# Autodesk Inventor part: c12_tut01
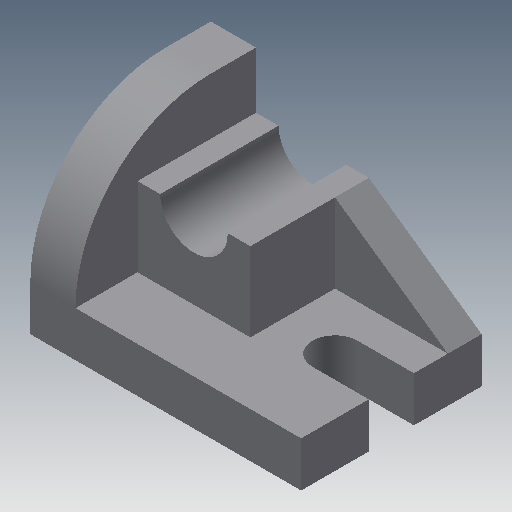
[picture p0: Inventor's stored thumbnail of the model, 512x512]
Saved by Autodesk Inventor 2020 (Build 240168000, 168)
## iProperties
Created: 2001-11
Part Number: c12_tut01
Document SubType Name: Modeling
Designer: Renu Muthoo
Density: 1 g/cm^3
Material: Generic
Appearance: Default
Control State: 0
Master: False
Checked Out: False
Shininess: 77.0
Length Units: 11269
Angle Units: 11279
Time Units: 11290
Mass Units: 11283
Length Display Precision: 3
Angle Display Precision: 2
Density: 0.0
Volumn: 0.0
Area: 0.0
PropertySet Name: Model Information
Author: Renu Muthoo
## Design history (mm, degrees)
sketch "Sketch1"
  geometry: L1 (-48, 36)-(48, 36); L2 (48, -28)-(-48, -28); L3 (-48, -28)-(-48, 36); L4 (48, 12)-(28, 12); L5 (28, -4)-(48, -4); L6 (48, 36)-(48, 12); L7 (48, -4)-(48, -28); A1 r 8 centre (28, 4) between (28, 12) and (28, -4)
  constraints: 14 end point, 4 parallel, 3 perpendicular, 2 point on circle, 2 tangent, 1 centre point, 1 collinear, 1 horizontal
  dimensions: "d0" = 96 distance of L2.start L2.end; "d1" = 64 distance of L2.end L1.start; "d2" = 20 distance of L4.start L4.end; "d3" = 24 distance between parallel lines of L2 L5; "d4" = 16 distance between parallel lines of L4 L5
extrude "Extrusion1" new body sketch "Sketch1" distance "d5" = 16; taper "d6" = 0 deg
sketch "Sketch2"
  geometry: L1 (16, 64)-(64, 64); L2 (64, 64)-(64, 48); L3 (16, 0)-(16, 0); L4 (16, 0)-(16, 64); L5 (0, 64)-(16, 64) reference; L6 (16, 0)-(16, 64) reference; L7 (0, 0)-(16, 0) reference; L8 (0, 0)-(0, 64) reference; A1 r 48 centre (16, 48) between (16, 0) and (64, 48)
  constraints: 8 end point, 3 collinear, 3 perpendicular, 2 point on circle, 2 tangent, 1 centre point, 1 horizontal
  dimensions: "d7" = 64 distance between parallel lines of L2 L8; "d8" = 48 radius of A1
extrude "Extrusion2" join sketch "Sketch2" distance "d9" = 16; taper "d10" = 0 deg
sketch "Sketch3"
  geometry: L1 (16, -44)-(16, -16); L2 (16, -16)-(56, -16); L3 (56, -16)-(56, -44); L4 (56, -44)-(48, -44); L5 (24, -44)-(16, -44); L6 (16, -64)-(16, -16) reference; L7 (16, -16)-(96, -16) reference; A1 r 12 centre (36, -44) between (48, -44) and (24, -44)
  constraints: 10 end point, 3 collinear, 3 parallel, 2 equal length, 2 point on circle, 1 centre point, 1 perpendicular, 1 point on line, 1 vertical
  dimensions: "d11" = 28 distance of L2.end L3.end; "d12" = 8 distance of L3.end L4.end; "d13" = 24 distance of L5.start L4.end
extrude "Extrusion3" join sketch "Sketch3" distance "d14" = 42; taper "d15" = 0 deg
sketch "Sketch4"
  geometry: L1 (56, -16)-(96, -16) reference; L2 (56, -16)-(56, -44) reference; L3 (96, -16)-(56, -44)
  constraints: 2 end point
extrude "Extrusion4" join sketch "Sketch4" distance "d16" = 12; taper "d17" = 0 deg
body "Solid1"
